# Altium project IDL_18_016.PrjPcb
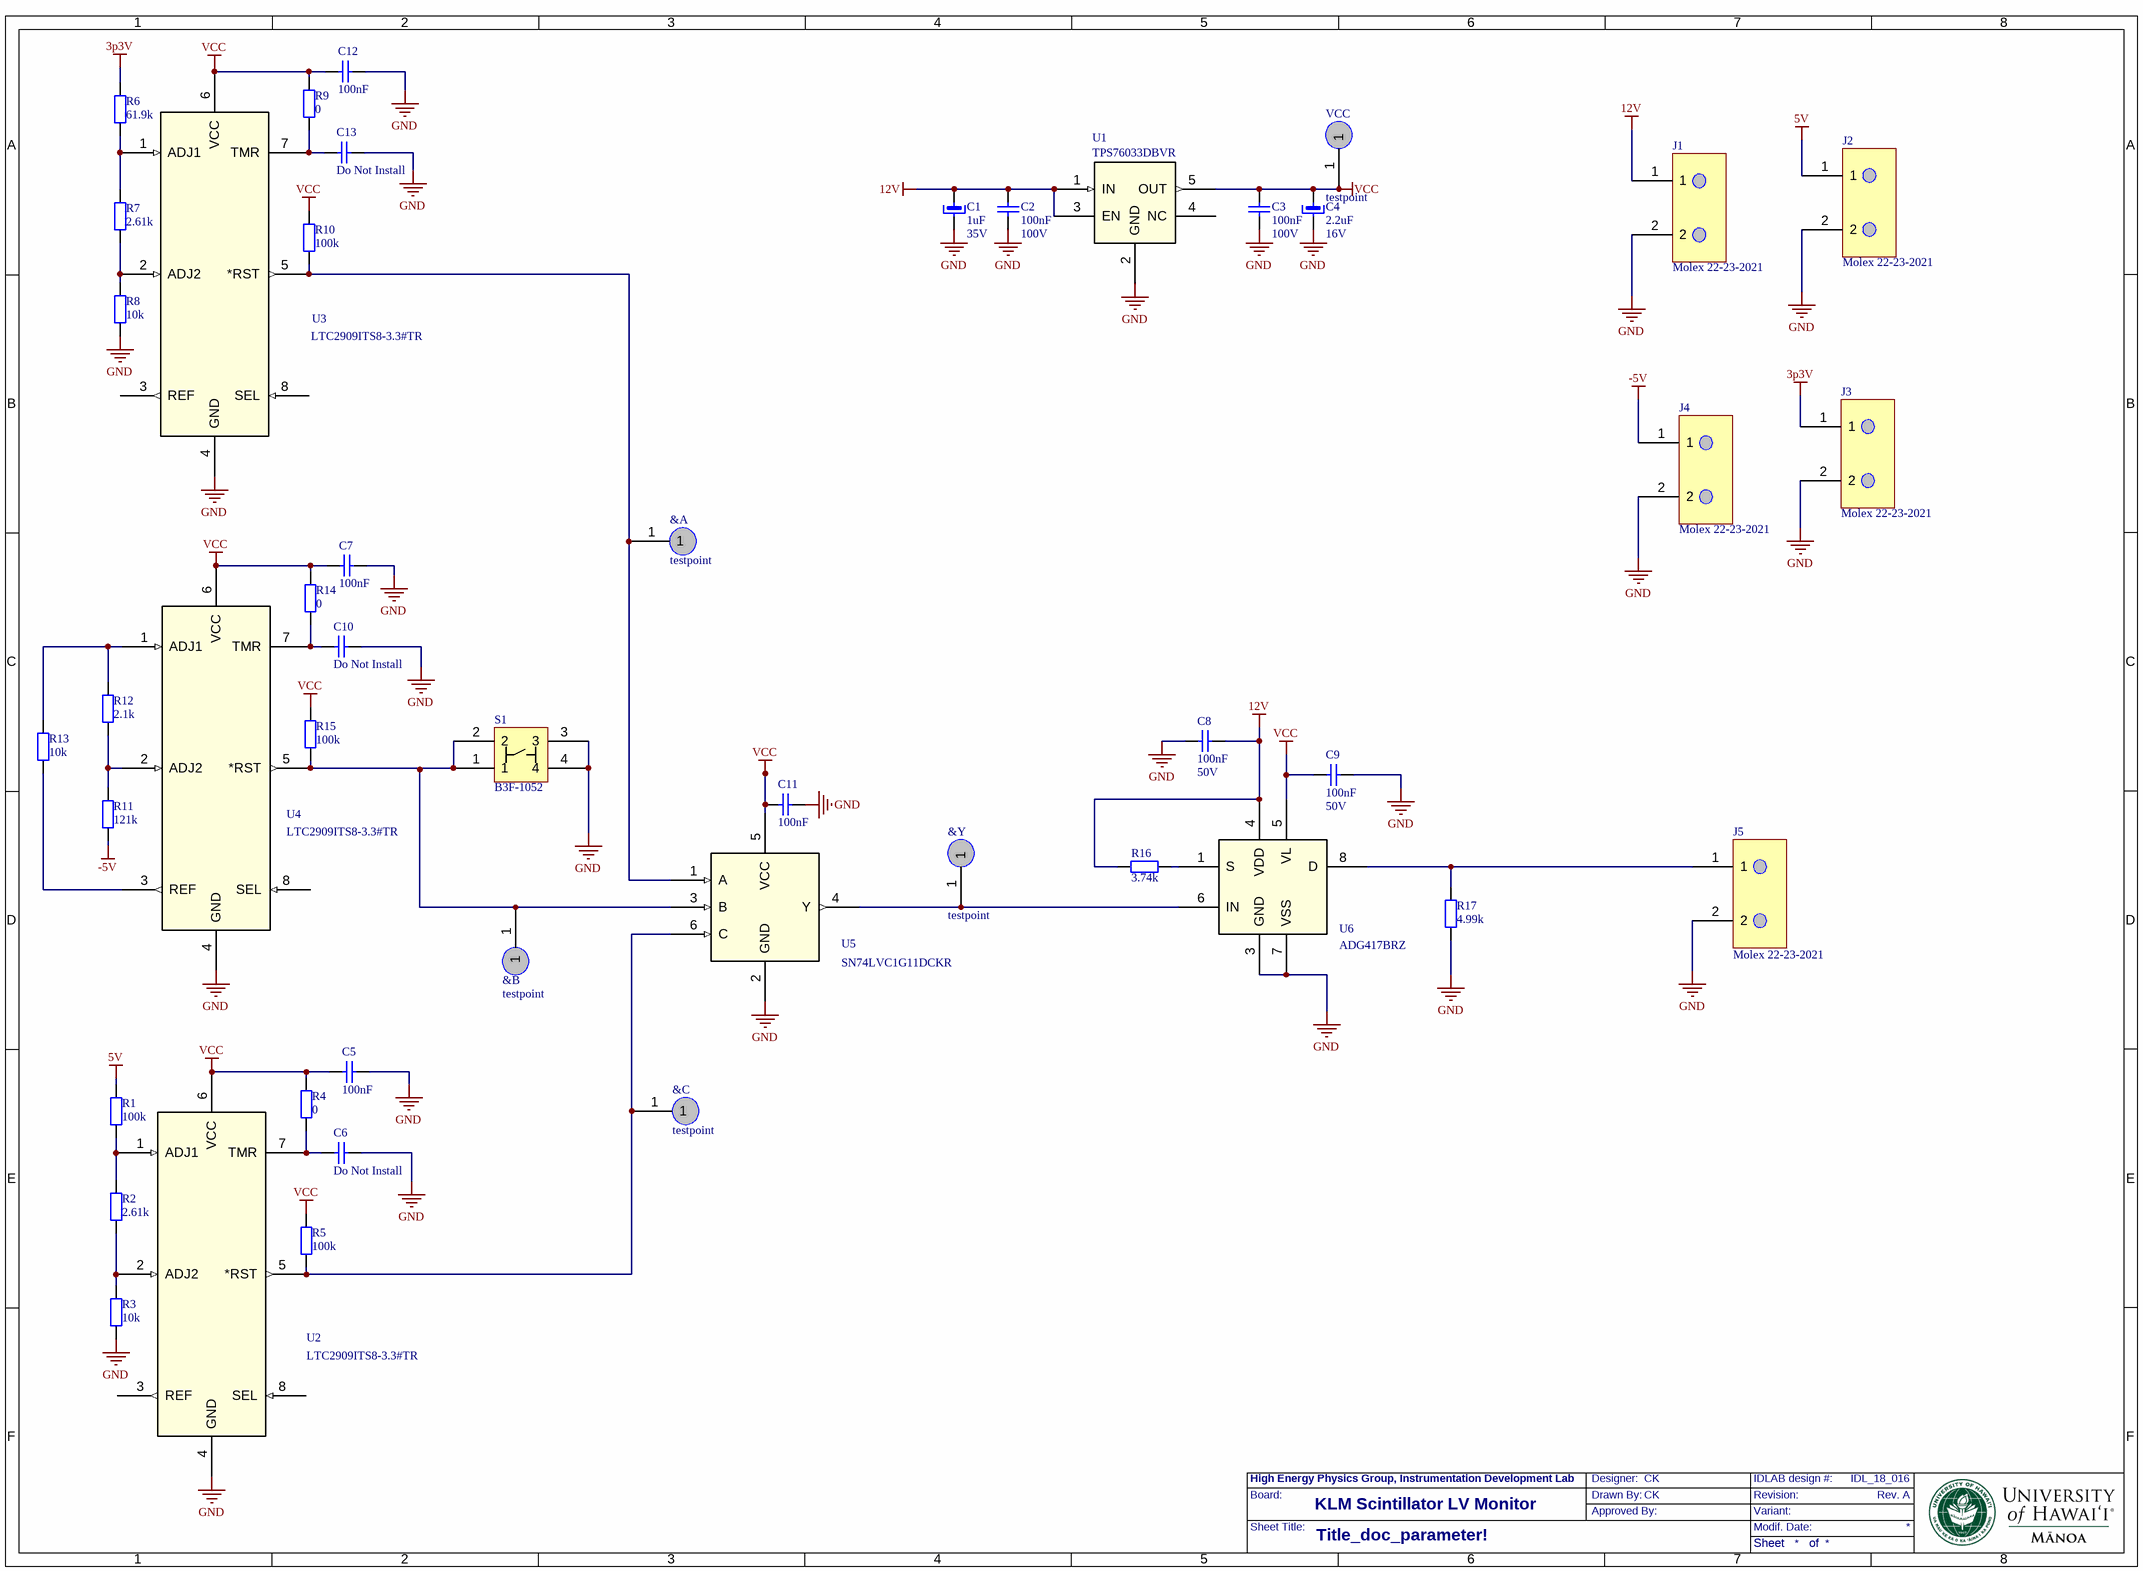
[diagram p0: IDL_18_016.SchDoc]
BoardName: KLM Scintillator LV Monitor; Designer: CK; Drawn_By: CK; IDLnum: IDL_18_016; RevNum: Rev. A; Title_doc_parameter: Circuit Schematics
1 sheet, 47 parts. Net scope: global (net labels, ports and power ports of the same name join across sheets).
Board file: IDL_18_016.PcbDoc

## Sheet IDL_18_016.SchDoc: Title_doc_parameter!
size 401 x 291 mm

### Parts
&A  testpoint  [testpoint]
&B  testpoint  [testpoint]
&C  testpoint  [testpoint]
&Y  testpoint  [testpoint]
C1  1uF  Voltage rating: 35V  [CTC-A3216-18]
C2  100nF  Voltage rating: 100V  [CC0603RF1R]
C3  100nF  Voltage rating: 100V  [CC0603RF1R]
C4  2.2uF  Voltage rating: 16V  [CTC-A3216-18]
C5  100nF  [CC0603RF1R]
C6  Do Not Install  [CC0603RF1R]
C7  100nF  [CC0603RF1R]
C8  100nF  Voltage rating: 50V  [CC0603RF1R]
C9  100nF  Voltage rating: 50V  [CC0603RF1R]
C10  Do Not Install  [CC0603RF1R]
C11  100nF  [CC0603RF1R]
C12  100nF  [CC0603RF1R]
C13  Do Not Install  [CC0603RF1R]
J1  Molex 22-23-2021  [32_MMBX-50-0-4]
J2  Molex 22-23-2021  [32_MMBX-50-0-4]
J3  Molex 22-23-2021  [32_MMBX-50-0-4]
J4  Molex 22-23-2021  [32_MMBX-50-0-4]
J5  Molex 22-23-2021  [32_MMBX-50-0-4]
R1  100k  [RC0603N1R]
R2  2.61k  [RC0603N1R]
R3  10k  [RC0603N1R]
R4  0  [RC0603N1R]
R5  100k  [RC0603N1R]
R6  61.9k  [RC0603N1R]
R7  2.61k  [RC0603N1R]
R8  10k  [RC0603N1R]
R9  0  [RC0603N1R]
R10  100k  [RC0603N1R]
R11  121k  [RC0603N1R]
R12  2.1k  [RC0603N1R]
R13  10k  [RC0603N1R]
R14  0  [RC0603N1R]
R15  100k  [RC0603N1R]
R16  3.74k  [RC0603N1R]
R17  4.99k  [RC0603N1R]
S1  B3F-1052  [B3F-1052]
U1  TPS76033DBVR  [DBV5]
U2  LTC2909ITS8-3.3#TR  [TSOT-23_TS8]
U3  LTC2909ITS8-3.3#TR  [TSOT-23_TS8]
U4  LTC2909ITS8-3.3#TR  [TSOT-23_TS8]
U5  SN74LVC1G11DCKR  [DCK6]
U6  ADG417BRZ  [R_8]
VCC  testpoint  [testpoint]

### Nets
3p3V: J3.1 R6.2
5V: J2.1 R1.2
12V: C1.1 C2.2 C8.2 J1.1 R16.1 U1.1(IN) U1.3(EN) U6.4(VDD)
-5V: J4.1 R11.2
GND: C1.2 C2.1 C3.1 C4.2 C5.1 C6.1 C7.1 C8.1 C9.2 C10.1 C11.1 C12.1 C13.1 J1.2 J2.2 J3.2 J4.2 J5.2 R3.1 R8.1 R17.1 S1.3 S1.4 U1.2(GND) U2.4(GND) U3.4(GND) U4.4(GND) U5.2(GND) U6.3(GND) U6.7(VSS)
VCC: C3.2 C4.1 C5.2 C7.2 C9.1 C11.2 C12.2 R4.2 R5.2 R9.2 R10.2 R14.2 R15.2 U1.5(OUT) U2.6(VCC) U3.6(VCC) U4.6(VCC) U5.5(VCC) U6.5(VL) VCC.1
Net&A_1: &A.1 R10.1 U3.5(*RST) U5.1(A)
Net&B_1: &B.1 R15.1 S1.1 S1.2 U4.5(*RST) U5.3(B)
Net&C_1: &C.1 R5.1 U2.5(*RST) U5.6(C)
Net&Y_1: &Y.1 U5.4(Y) U6.6(IN)
NetC6_2: C6.2 R4.1 U2.7(TMR)
NetC10_2: C10.2 R14.1 U4.7(TMR)
NetC13_2: C13.2 R9.1 U3.7(TMR)
NetJ5_1: J5.1 R17.2 U6.8(D)
NetR1_1: R1.1 R2.2 U2.1(ADJ1)
NetR2_1: R2.1 R3.2 U2.2(ADJ2)
NetR6_1: R6.1 R7.2 U3.1(ADJ1)
NetR7_1: R7.1 R8.2 U3.2(ADJ2)
NetR11_1: R11.1 R12.1 U4.2(ADJ2)
NetR12_2: R12.2 R13.1 U4.1(ADJ1)
NetR13_2: R13.2 U4.3(REF)
NetR16_2: R16.2 U6.1(S)

Not connected (* = marked no-connect by the designer): U1 4(NC); U2 3(REF) 8(SEL); U3 3(REF) 8(SEL); U4 8(SEL)

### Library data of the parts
C1 = CAPT3216_1U_35V: Capacitor tantal smd 3216-18 35V 7.5Resr; Manufacturer: KEMET; Manufacturer No: T491A105K035AT; Tech: SMDR
C2 C3 = CAPCC0603_1_100N_100VX7R: Capacitor chip ceramic 0603 100V X7R; Manufacturer: Murata; Manufacturer No: GRM188R72A104KA35D; Tech: SMDR
C4 = CAPT3216_2.2U_16V: Capacitor tantal smd 3216-18 16V 6.5Resr; Manufacturer: AVX; Manufacturer No: TAJA225K016R; Tech: SMDR
C5-C13 = CAPCC0603_1_100N_50VX7R: Capacitor chip ceramic 0603 50V X7R; Manufacturer: Murata; Manufacturer No: GRM188R71H104KA93D; Tech: SMDR
J1-J5 = Molex 22-23-2021: KK 100 Header Assy
R1-R3 R5-R8 R10-R13 R15 = PR_RES0603-1_100k-0.1%25PPM: Chip Resistor 0603 100mW 0.1% 25ppm; Manufacturer: Panasonic; Manufacturer No: ERA-3AEB104V; Tech: SMDR
R4 R9 R14 R16 R17 = PR_RES0603-1_4.99k-0.1%25PPM: Chip Resistor 0603 100mW 0.1% 25ppm; Manufacturer: Panasonic; Manufacturer No: ERA-3AEB4991V; Tech: SMDR
S1 = B3F-1052: Switch Tactile 0.5A 24V SW405-ND
U1 = TPS76033DBVR: Imported; Vendor: Texas Instruments; Built_By: EMA_UL_Team; C: Copyright (C) 2015 Accelerated Designs. All rights reserved
U2-U4 = LTC2909ITS8-3.3#TR: IC MONITOR PREC 3.3V TSOT23-8 LTC2909ITS8-3.3#TRMPBFCT-ND; Manufacturer_Part_Number: LTC2909ITS8-5#TRMPBF; Vendor: Linear Technology; Built_By: EMA_UL_Team
U5 = SN74LVC1G11DCKR: Imported; Manufacturer: Texas Instruments; Built_By: EMA_UL_Team; C: Copyright (C) 2015 Accelerated Designs. All rights reserved
U6 = ADG417BRZ: Analog Switch; Vendor: Analog Devices Inc; Built_By: EMA_UL_Team; C: Copyright (C) 2015 Accelerated Designs. All rights reserved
